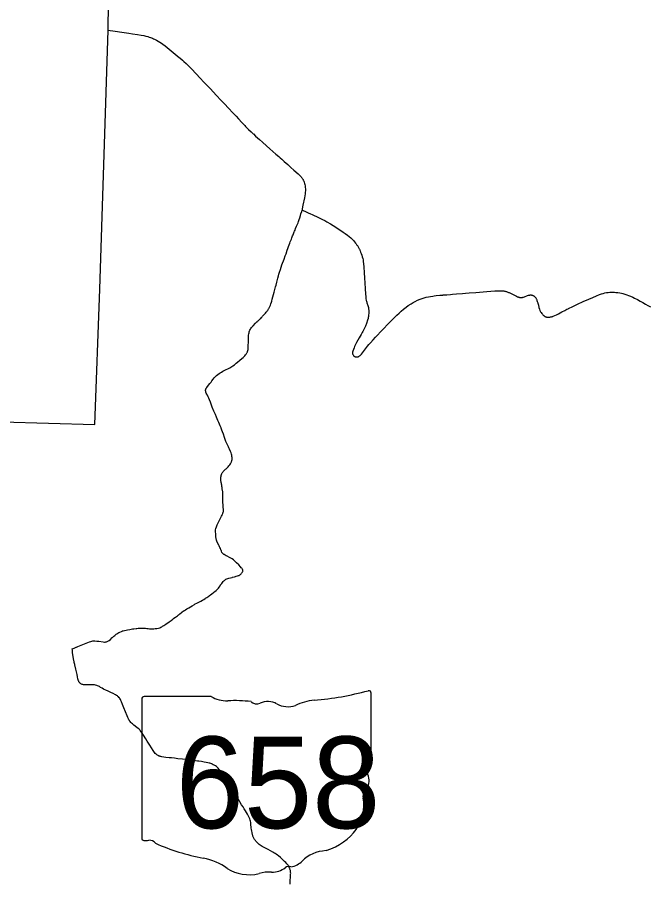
# Model space of a CAD drawing. Extents: x 1761803 to 2441803, y 509895 to 949895.
# Drawn here: x 2197858 to 2217062, y 865604 to 891870 of the extents above; entities that cross this region are included whole.
import ezdxf

# ---------------------------------------------------------------- set-up
doc = ezdxf.new("R2010")
doc.units = 0
for name, color, linetype in [('GM_X_County', 7, 'Continuous'), ('GM_X_Minor_Lake', 7, 'Continuous'), ('GM_X_Township_Road', 7, 'Continuous')]:
    doc.layers.add(name, color=color, linetype=linetype)

msp = doc.modelspace()

# ---------------------------------------------------------------- linework, layer by layer
at = {"layer": 'GM_X_County'}
msp.add_lwpolyline([(2197403, 879594), (2200215, 879512), (2200360, 883620), (2200613, 891485), (2200641, 893124), (2200753, 895343), (2200888, 899628), (2200970, 901426), (2200980, 901737), (2200952, 902861), (2200950, 903740), (2200937, 905583), (2203468, 905454), (2205367, 905447), (2208877, 905314), (2211708, 905261), (2213519, 905293)], dxfattribs=at)
at = {"layer": 'GM_X_Minor_Lake'}
for points in [[(2200608, 891484), (2200827, 891452), (2201034, 891420), (2201242, 891389), (2201359, 891372), (2201512, 891349), (2201618, 891331), (2201696, 891316), (2201757, 891302), (2201820, 891284), (2201861, 891272), (2201905, 891257), (2201934, 891247), (2201963, 891235), (2201995, 891221), (2202023, 891208), (2202082, 891178), (2202137, 891147), (2202187, 891117), (2202234, 891086), (2202279, 891053), (2202347, 891001), (2202533, 890850), (2202772, 890655), (2202789, 890641)], [(2202789, 890641), (2202871, 890574), (2202918, 890533), (2202990, 890465), (2203039, 890417), (2203085, 890371), (2203110, 890345), (2203146, 890307), (2203420, 890015), (2203517, 889912), (2203626, 889798), (2203713, 889705), (2203811, 889599), (2203901, 889503), (2204048, 889349), (2204150, 889242), (2204271, 889113), (2204404, 888972), (2204500, 888868), (2204578, 888784), (2204675, 888682), (2204769, 888582), (2204792, 888558), (2204879, 888469), (2204956, 888393), (2205020, 888335), (2205026, 888329), (2205094, 888267), (2205212, 888163), (2205305, 888080), (2205426, 887970), (2205527, 887881), (2205618, 887801), (2205712, 887718), (2205796, 887645), (2205840, 887606), (2205887, 887565), (2205965, 887496), (2206069, 887405), (2206169, 887315), (2206256, 887235), (2206385, 887119), (2206394, 887110), (2206430, 887075), (2206464, 887040), (2206477, 887026), (2206488, 887012), (2206500, 886997), (2206510, 886983), (2206519, 886970), (2206528, 886956), (2206536, 886943), (2206542, 886929), (2206550, 886913), (2206558, 886896), (2206561, 886889)], [(2206561, 886889), (2206565, 886880), (2206571, 886862), (2206581, 886828), (2206589, 886799), (2206596, 886756), (2206602, 886711), (2206605, 886658), (2206605, 886633), (2206605, 886608), (2206603, 886566), (2206597, 886513), (2206589, 886454), (2206577, 886390), (2206530, 886165), (2206511, 886059), (2206504, 886019)], [(2204201, 878166), (2204210, 878173), (2204236, 878198), (2204262, 878228), (2204286, 878258), (2204310, 878288), (2204329, 878314), (2204343, 878339), (2204354, 878359), (2204361, 878374), (2204367, 878391), (2204370, 878405), (2204374, 878421), (2204378, 878447), (2204380, 878477), (2204379, 878514), (2204377, 878543), (2204370, 878579), (2204361, 878615), (2204348, 878652), (2204334, 878690), (2204303, 878760), (2204283, 878807), (2204268, 878835), (2204243, 878889), (2204214, 878953), (2204193, 879000), (2204171, 879058), (2204149, 879116), (2204115, 879220), (2204091, 879285), (2204073, 879338), (2204051, 879396), (2204046, 879409), (2204022, 879470), (2203977, 879572), (2203950, 879635), (2203911, 879733), (2203876, 879818), (2203831, 879920), (2203780, 880037), (2203757, 880095), (2203721, 880186), (2203693, 880262), (2203671, 880313), (2203652, 880354), (2203630, 880399), (2203606, 880445), (2203600, 880455), (2203596, 880464), (2203592, 880474), (2203588, 880483), (2203585, 880493), (2203584, 880499), (2203581, 880509), (2203579, 880522), (2203578, 880530), (2203577, 880542), (2203577, 880550), (2203578, 880561), (2203580, 880572), (2203581, 880578), (2203583, 880586), (2203586, 880592), (2203590, 880602), (2203594, 880610), (2203600, 880620), (2203609, 880632), (2203665, 880701), (2203705, 880751), (2203744, 880801), (2203770, 880835), (2203810, 880890), (2203838, 880925), (2203856, 880945), (2203879, 880966), (2203909, 880994), (2203948, 881026), (2203988, 881058), (2204018, 881079), (2204054, 881101), (2204103, 881127), (2204163, 881161), (2204200, 881178), (2204253, 881203), (2204312, 881234), (2204346, 881254), (2204373, 881272), (2204403, 881291), (2204451, 881326), (2204505, 881371), (2204542, 881401), (2204617, 881460), (2204680, 881512), (2204716, 881543), (2204745, 881570), (2204769, 881596), (2204791, 881622), (2204807, 881646), (2204823, 881670), (2204832, 881684), (2204839, 881699), (2204845, 881714), (2204850, 881726), (2204858, 881757), (2204864, 881789), (2204870, 881831), (2204871, 881875), (2204873, 881929), (2204874, 881992), (2204875, 882115), (2204879, 882185), (2204883, 882221), (2204888, 882259), (2204894, 882291), (2204902, 882322), (2204912, 882352), (2204924, 882379), (2204937, 882405), (2204952, 882429), (2204969, 882453), (2204992, 882480), (2205019, 882509), (2205096, 882585), (2205136, 882623), (2205146, 882632), (2205157, 882644), (2205174, 882659), (2205190, 882675), (2205230, 882714), (2205249, 882732), (2205271, 882756), (2205291, 882778), (2205309, 882797), (2205318, 882806), (2205369, 882861), (2205393, 882888), (2205416, 882916), (2205441, 882947), (2205460, 882974), (2205473, 882993), (2205481, 883005), (2205488, 883018), (2205499, 883036), (2205508, 883051), (2205516, 883068), (2205527, 883091), (2205544, 883134), (2205560, 883177), (2205576, 883228), (2205584, 883255), (2205602, 883315), (2205622, 883391), (2205657, 883523), (2205681, 883609), (2205703, 883690), (2205718, 883744), (2205742, 883834), (2205774, 883954), (2205792, 884025), (2205805, 884072), (2205822, 884130), (2205848, 884219), (2205868, 884287), (2205895, 884361), (2205957, 884527), (2205996, 884633), (2206018, 884696), (2206055, 884799), (2206074, 884851), (2206098, 884916), (2206116, 884965), (2206132, 885013), (2206147, 885055), (2206165, 885100), (2206181, 885139), (2206195, 885173), (2206219, 885233), (2206233, 885267), (2206259, 885330), (2206269, 885354), (2206279, 885379), (2206292, 885409), (2206311, 885457), (2206340, 885526), (2206383, 885631), (2206399, 885677), (2206419, 885731), (2206437, 885786), (2206458, 885852), (2206472, 885901), (2206494, 885980), (2206504, 886019)], [(2206504, 886019), (2206587, 885986), (2206711, 885930), (2206739, 885917), (2206831, 885873), (2206982, 885801), (2207124, 885733), (2207192, 885699), (2207261, 885662), (2207369, 885600), (2207448, 885552), (2207588, 885460), (2207749, 885353), (2207817, 885306), (2207883, 885257), (2207936, 885213), (2207984, 885173), (2208027, 885132), (2208064, 885095), (2208099, 885055), (2208132, 885014), (2208146, 884996), (2208160, 884978), (2208173, 884959), (2208185, 884940), (2208198, 884921), (2208212, 884899), (2208222, 884882), (2208231, 884865), (2208242, 884845), (2208249, 884830), (2208255, 884817), (2208261, 884803), (2208271, 884779), (2208285, 884745), (2208300, 884705), (2208318, 884652), (2208335, 884596), (2208348, 884548), (2208357, 884506), (2208364, 884460), (2208373, 884392), (2208380, 884300), (2208392, 884117), (2208402, 883963), (2208422, 883642), (2208433, 883465), (2208439, 883393), (2208447, 883328), (2208454, 883287), (2208456, 883276)], [(2208456, 883276), (2208461, 883255), (2208470, 883224), (2208477, 883202), (2208504, 883125), (2208513, 883096), (2208521, 883061), (2208524, 883044), (2208527, 883027), (2208528, 883010), (2208530, 882992), (2208531, 882949), (2208530, 882890), (2208527, 882834), (2208522, 882792), (2208517, 882759), (2208509, 882727), (2208492, 882673), (2208458, 882574), (2208430, 882500), (2208402, 882434), (2208376, 882377), (2208354, 882336), (2208335, 882302), (2208300, 882246), (2208239, 882142), (2208200, 882074), (2208162, 882004), (2208130, 881942), (2208102, 881880), (2208083, 881834), (2208066, 881789), (2208048, 881736), (2208041, 881706), (2208039, 881681), (2208040, 881665), (2208042, 881651), (2208044, 881644), (2208048, 881634), (2208053, 881622), (2208064, 881604), (2208077, 881589), (2208086, 881582), (2208095, 881576), (2208105, 881571), (2208120, 881565), (2208139, 881562), (2208159, 881560), (2208188, 881563), (2208194, 881564), (2208207, 881568), (2208218, 881571), (2208227, 881575), (2208252, 881591), (2208274, 881607), (2208290, 881621), (2208308, 881644), (2208341, 881686), (2208429, 881807), (2208490, 881885), (2208532, 881935), (2208582, 881992), (2208661, 882076), (2208740, 882159), (2208946, 882380), (2209145, 882589), (2209220, 882667), (2209291, 882740), (2209340, 882789), (2209385, 882832), (2209453, 882893), (2209514, 882948), (2209589, 883012), (2209663, 883072), (2209729, 883121), (2209815, 883177), (2209877, 883214), (2209938, 883245), (2210016, 883281), (2210089, 883311), (2210154, 883335), (2210213, 883354), (2210273, 883372), (2210341, 883387), (2210405, 883399), (2210477, 883410), (2210516, 883415), (2210581, 883422), (2210686, 883433), (2210781, 883441), (2210792, 883442), (2210849, 883446), (2210902, 883450), (2211013, 883460), (2211078, 883465), (2211193, 883474), (2211376, 883486), (2211467, 883494), (2211575, 883503), (2211778, 883520), (2212118, 883547), (2212236, 883556), (2212364, 883564), (2212469, 883569), (2212538, 883571), (2212571, 883570), (2212587, 883569), (2212604, 883567), (2212628, 883564), (2212652, 883559), (2212673, 883555), (2212694, 883550), (2212716, 883543), (2212738, 883537), (2212759, 883530), (2212779, 883522), (2212794, 883516), (2212796, 883516), (2212812, 883508), (2212857, 883487), (2212982, 883422), (2213017, 883404), (2213047, 883390), (2213063, 883383), (2213080, 883378), (2213098, 883373), (2213111, 883370), (2213124, 883368), (2213138, 883366), (2213153, 883366), (2213169, 883367), (2213183, 883368), (2213197, 883370), (2213211, 883373), (2213225, 883377), (2213256, 883387), (2213348, 883422), (2213380, 883433), (2213394, 883436), (2213409, 883439), (2213420, 883441), (2213432, 883442), (2213442, 883442), (2213453, 883442), (2213464, 883442), (2213476, 883440), (2213487, 883438), (2213499, 883435), (2213512, 883431), (2213523, 883426), (2213533, 883421), (2213542, 883416), (2213550, 883410), (2213564, 883400), (2213574, 883391), (2213583, 883381), (2213590, 883371), (2213597, 883362), (2213604, 883351), (2213611, 883340), (2213618, 883327), (2213625, 883313), (2213632, 883296), (2213639, 883279), (2213649, 883248), (2213663, 883204), (2213665, 883196), (2213681, 883134), (2213699, 883061), (2213713, 883014), (2213731, 882968), (2213751, 882931), (2213764, 882909), (2213786, 882880), (2213804, 882858), (2213818, 882843), (2213829, 882832), (2213838, 882824), (2213849, 882816), (2213858, 882808), (2213870, 882800), (2213880, 882793), (2213893, 882786), (2213903, 882782), (2213913, 882778), (2213924, 882774), (2213933, 882771), (2213945, 882769), (2213959, 882767), (2213972, 882766), (2213984, 882766), (2213995, 882767), (2214006, 882767), (2214019, 882769), (2214032, 882771), (2214049, 882774), (2214067, 882778), (2214084, 882783), (2214101, 882788), (2214118, 882794), (2214135, 882800), (2214181, 882819), (2214231, 882842), (2214295, 882875), (2214399, 882930), (2214486, 882976), (2214547, 883007), (2214584, 883025), (2214595, 883029), (2214731, 883093), (2214874, 883160), (2215046, 883241), (2215214, 883316), (2215331, 883368), (2215446, 883417), (2215534, 883452), (2215599, 883475), (2215652, 883492), (2215700, 883504), (2215749, 883514), (2215798, 883521), (2215847, 883526), (2215899, 883527), (2215958, 883526), (2215994, 883524), (2216037, 883521), (2216096, 883515), (2216154, 883506), (2216206, 883496), (2216251, 883486), (2216305, 883470), (2216364, 883450), (2216422, 883428), (2216483, 883403), (2216552, 883372), (2216605, 883346), (2216690, 883302), (2216773, 883255), (2216850, 883213), (2216933, 883166), (2217005, 883126), (2217091, 883078)], [(2204102, 877202), (2204104, 877273), (2204103, 877347), (2204102, 877380), (2204101, 877413), (2204098, 877446), (2204095, 877472), (2204082, 877560), (2204075, 877602), (2204070, 877634), (2204064, 877667), (2204059, 877696), (2204054, 877721), (2204049, 877747), (2204045, 877773), (2204042, 877789), (2204041, 877801), (2204038, 877821), (2204035, 877856), (2204035, 877878), (2204038, 877911), (2204044, 877942), (2204050, 877968), (2204060, 877995), (2204072, 878021), (2204083, 878041), (2204097, 878062), (2204114, 878084), (2204131, 878103), (2204185, 878152), (2204201, 878166)], [(2206141, 865561), (2206140, 865616), (2206143, 865673), (2206153, 865773), (2206158, 865822), (2206158, 865824), (2206159, 865859), (2206160, 865894), (2206159, 865910), (2206154, 865955), (2206150, 865977), (2206146, 865994), (2206139, 866019), (2206134, 866032), (2206128, 866047), (2206116, 866075), (2206103, 866100), (2206082, 866131), (2206065, 866156), (2206044, 866181), (2206013, 866214), (2205976, 866250), (2205935, 866288), (2205907, 866312), (2205847, 866365), (2205788, 866416), (2205755, 866442), (2205719, 866470), (2205686, 866493), (2205650, 866514), (2205615, 866533), (2205549, 866568), (2205471, 866608), (2205411, 866640), (2205336, 866678), (2205290, 866703), (2205259, 866723), (2205229, 866743), (2205203, 866763), (2205163, 866800), (2205138, 866823), (2205113, 866851), (2205099, 866868), (2205088, 866882), (2205073, 866903), (2205063, 866918), (2205043, 866952), (2205032, 866974), (2205024, 866991), (2205015, 867011), (2205010, 867027), (2205006, 867038), (2205001, 867056), (2204998, 867070), (2204987, 867121), (2204976, 867179), (2204973, 867200), (2204963, 867284), (2204954, 867370), (2204949, 867409), (2204945, 867432), (2204938, 867468), (2204930, 867499), (2204917, 867543), (2204902, 867584), (2204882, 867627), (2204852, 867683), (2204820, 867737), (2204786, 867788), (2204749, 867846), (2204713, 867903), (2204670, 867969), (2204615, 868058), (2204573, 868124), (2204494, 868252), (2204401, 868400), (2204333, 868509), (2204306, 868550), (2204292, 868572), (2204278, 868595), (2204232, 868663), (2204216, 868687), (2204189, 868729), (2204141, 868805), (2204119, 868848), (2204105, 868872), (2204088, 868903), (2204075, 868924), (2204062, 868945), (2204045, 868970), (2204032, 868988), (2204012, 869013), (2203987, 869044), (2203959, 869075), (2203934, 869100), (2203903, 869126), (2203872, 869149), (2203837, 869171), (2203808, 869186), (2203779, 869200), (2203764, 869207), (2203732, 869219), (2203700, 869230), (2203685, 869235), (2203648, 869245), (2203596, 869256), (2203537, 869267), (2203453, 869280), (2203375, 869290), (2203330, 869295), (2203267, 869303), (2203167, 869315), (2203088, 869324), (2203036, 869330), (2202876, 869351), (2202733, 869368), (2202630, 869380), (2202537, 869390), (2202473, 869396), (2202368, 869407), (2202306, 869415), (2202251, 869424), (2202219, 869431), (2202197, 869437), (2202188, 869440), (2202168, 869447), (2202160, 869450), (2202142, 869459), (2202134, 869463), (2202113, 869475), (2202095, 869489), (2202075, 869506), (2202049, 869530), (2202027, 869555), (2202002, 869586), (2201983, 869613), (2201930, 869696), (2201878, 869780), (2201806, 869897), (2201760, 869969), (2201693, 870078), (2201673, 870108), (2201653, 870138), (2201621, 870183), (2201593, 870219), (2201574, 870242), (2201554, 870262), (2201525, 870288), (2201488, 870318), (2201401, 870384), (2201356, 870421), (2201327, 870446), (2201304, 870470), (2201284, 870492), (2201271, 870510), (2201267, 870516), (2201262, 870523), (2201251, 870540), (2201244, 870551), (2201231, 870576), (2201212, 870616), (2201192, 870667), (2201093, 870913), (2201053, 871014), (2201020, 871096), (2201006, 871129), (2200999, 871144), (2200987, 871167), (2200973, 871191), (2200960, 871210), (2200952, 871219), (2200935, 871240), (2200915, 871258), (2200897, 871272), (2200875, 871286), (2200842, 871305), (2200765, 871342), (2200694, 871375), (2200614, 871413), (2200546, 871446), (2200499, 871470), (2200479, 871481), (2200436, 871505), (2200388, 871533), (2200351, 871555), (2200320, 871571), (2200296, 871581), (2200269, 871591), (2200237, 871600), (2200205, 871606), (2200174, 871610), (2200137, 871611), (2200066, 871610), (2200003, 871607), (2199946, 871606), (2199911, 871606), (2199869, 871611), (2199845, 871616), (2199829, 871620), (2199807, 871629), (2199791, 871637), (2199782, 871643), (2199773, 871650), (2199763, 871658), (2199752, 871670), (2199745, 871678), (2199738, 871690), (2199729, 871705), (2199722, 871722), (2199717, 871735), (2199711, 871756), (2199701, 871791), (2199689, 871850), (2199688, 871852), (2199673, 871920), (2199654, 872000), (2199633, 872087), (2199622, 872131), (2199617, 872153), (2199600, 872225), (2199586, 872289), (2199583, 872308), (2199566, 872402), (2199545, 872525), (2199538, 872578), (2199534, 872607), (2199531, 872642), (2199529, 872665), (2199527, 872700), (2199583, 872725), (2199603, 872735), (2199626, 872746), (2199641, 872752), (2199651, 872756), (2199672, 872763), (2199696, 872774), (2199802, 872816), (2199894, 872852), (2199997, 872894), (2200053, 872916), (2200090, 872928), (2200126, 872937), (2200148, 872941), (2200172, 872944), (2200211, 872944), (2200274, 872938), (2200332, 872931), (2200468, 872912), (2200501, 872909), (2200523, 872909), (2200546, 872911), (2200564, 872914), (2200586, 872921), (2200606, 872930), (2200625, 872941), (2200646, 872957), (2200684, 872988), (2200742, 873041), (2200751, 873050), (2200773, 873070), (2200792, 873088), (2200815, 873107), (2200858, 873143), (2200885, 873162), (2200913, 873179), (2200945, 873197), (2200975, 873211), (2201020, 873231), (2201039, 873238), (2201057, 873244), (2201073, 873249), (2201114, 873259), (2201159, 873269), (2201208, 873279), (2201275, 873293), (2201315, 873299), (2201356, 873306), (2201401, 873313), (2201463, 873320), (2201489, 873323), (2201528, 873327), (2201544, 873329), (2201570, 873330), (2201596, 873331), (2201635, 873333), (2201655, 873334), (2201685, 873333), (2201707, 873331), (2201724, 873329), (2201753, 873325), (2201792, 873321), (2201834, 873315), (2201876, 873311), (2201912, 873308), (2201954, 873308), (2202000, 873311), (2202045, 873316), (2202097, 873324), (2202142, 873333), (2202182, 873344), (2202219, 873358), (2202245, 873371), (2202270, 873385), (2202311, 873412), (2202373, 873455), (2202466, 873523), (2202527, 873567), (2202583, 873606), (2202612, 873628), (2202665, 873666), (2202718, 873705), (2202752, 873731), (2202759, 873737), (2202790, 873762), (2202837, 873798), (2202852, 873810), (2202907, 873851), (2202934, 873870), (2202962, 873888), (2203009, 873917), (2203063, 873948), (2203165, 874008), (2203235, 874049), (2203261, 874063), (2203305, 874086), (2203351, 874110), (2203427, 874148), (2203482, 874177), (2203522, 874200), (2203566, 874228), (2203577, 874235), (2203615, 874260), (2203644, 874281), (2203673, 874303), (2203699, 874323), (2203726, 874342), (2203762, 874369), (2203807, 874403), (2203830, 874420), (2203856, 874440), (2203899, 874476), (2203913, 874489), (2203945, 874522), (2203966, 874547), (2203989, 874578), (2204016, 874615), (2204028, 874634), (2204031, 874640), (2204065, 874689), (2204085, 874715), (2204106, 874741), (2204129, 874765), (2204146, 874780), (2204172, 874801), (2204192, 874812), (2204216, 874824), (2204250, 874838), (2204279, 874847), (2204333, 874861), (2204378, 874872), (2204397, 874876), (2204451, 874889), (2204454, 874889), (2204479, 874896), (2204508, 874903), (2204549, 874913), (2204579, 874924), (2204594, 874931), (2204616, 874943), (2204636, 874959), (2204653, 874974), (2204670, 874994), (2204681, 875009), (2204690, 875023), (2204697, 875037), (2204703, 875052), (2204705, 875066), (2204706, 875075), (2204706, 875085), (2204705, 875090), (2204703, 875098), (2204699, 875107), (2204693, 875118), (2204686, 875129), (2204673, 875148), (2204658, 875165), (2204632, 875194), (2204581, 875249), (2204517, 875313), (2204487, 875343), (2204452, 875376), (2204420, 875404), (2204387, 875430), (2204345, 875455), (2204302, 875478), (2204232, 875512), (2204199, 875528), (2204170, 875542), (2204135, 875563), (2204127, 875568), (2204097, 875595), (2204073, 875626), (2204055, 875665), (2204044, 875692), (2204037, 875710), (2204025, 875744), (2204011, 875777), (2204002, 875798), (2203988, 875827), (2203980, 875845), (2203942, 875924), (2203921, 875967), (2203908, 876005), (2203897, 876053), (2203891, 876102), (2203887, 876154), (2203883, 876199), (2203880, 876248), (2203878, 876281), (2203880, 876310), (2203891, 876352), (2203909, 876405), (2203932, 876465), (2203950, 876510), (2203967, 876550), (2203985, 876587), (2204027, 876664), (2204062, 876724), (2204079, 876758), (2204083, 876766), (2204099, 876805), (2204104, 876824), (2204111, 876846), (2204115, 876872), (2204117, 876897), (2204118, 876933), (2204114, 876999), (2204110, 877054), (2204104, 877161), (2204102, 877202)]]:
    msp.add_lwpolyline(points, dxfattribs=at)
at = {"layer": 'GM_X_Township_Road'}
for p, q in [((2208602, 869150), (2208602, 871361)), ((2201641, 871183), (2201641, 866957)), ((2203748, 871256), (2201709, 871256)), ((2208601, 869150), (2208602, 869150))]:
    msp.add_line(p, q, dxfattribs=at)
for centre, major_axis, start_param, end_param in [((2206122, 877018), (7382, 0), 4.814394, 5.042369), ((2208524, 871370), (77.5, 0), 6.141152, 7.989035), ((2201721, 871192), (80.6, 0), 1.712693, 3.28349), ((2204233, 871747), (782, 0), 4.042523, 4.731795), ((2204493, 868883), (2808, 0), 1.404758, 1.657858), ((2205130, 871214), (226, 0), 3.836095, 5.185415), ((2205461, 870726), (469, 0), 0.950623, 2.079405), ((2206067, 871396), (564, 0), 4.081561, 5.145723), ((2207064, 869965), (1485, 0), 1.699011, 2.107814), ((2208584, 868987), (120, 0), 1.883978, 3.671073), ((2207821, 868708), (720, 0), 5.934695, 6.695948), ((2208519, 869141), (82.9, 0), 5.05454, 6.418171), ((2208879, 868224), (524, 0), 2.387724, 3.262537), ((2206536, 867943), (1846, 0), 5.101752, 6.440018), ((2201721, 866947), (81.4, 0), 3.00124, 4.508301), ((2201734, 867380), (621, 0), 4.665946, 4.897461), ((2201861, 866713), (224, 0), 0.519207, 1.627899), ((2204687, 870510), (5331, 0), 4.195997, 4.488961), ((2207314, 865770), (1011, 0), 1.647645, 2.488434), ((2203098, 865058), (1668, 0), 0.823519, 1.323587), ((2204902, 866692), (1058, 0), 4.026481, 4.996735), ((2205591, 866375), (564, 0), 4.691044, 5.507374), ((2206101, 865966), (159, 0), 1.147584, 2.315152), ((2206033, 866547), (597, 0), 4.937069, 5.64225), ((2205513, 865230), (870, 0), 1.495662, 1.94098)]:
    msp.add_ellipse(centre, major_axis=major_axis, ratio=0.8, start_param=start_param, end_param=end_param, dxfattribs=at)

# ---------------------------------------------------------------- texts
msp.add_text('658', height=2784.4, dxfattribs=at).set_placement((2202670, 867255))

doc.saveas('drawing.dxf')
